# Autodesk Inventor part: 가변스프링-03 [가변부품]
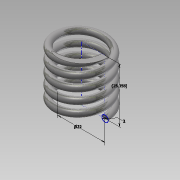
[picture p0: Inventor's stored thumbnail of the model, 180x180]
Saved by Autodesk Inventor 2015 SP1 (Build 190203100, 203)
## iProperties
Created: 2014-12
Part Number: 가변스프링-03 [가변부품]
Material: 강철, 탄소
Document SubType Name: Modeling
Designer: jhkwon
Density: 7.85 g/cm^3
Appearance: 반연마
Mass: 18.6941 g
Surface Area: 32.4032 cm^2
Volume: 2.38141 cm^3
Author: jhkwon
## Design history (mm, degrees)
sketch "스케치1"
  geometry: L1 (0, 0)-(-11, 0); L2 (-11, 0)-(-11, 25.358); L3 (-11, 25.358)-(0, 25.358); L4 (0, 25.358)-(0, 0); C1 r 1.5 at (-11, 0); 1 further point
  constraints: 8 end point, 2 coincident, 2 parallel, 1 centre point, 1 horizontal, 1 perpendicular
  dimensions: "d0" = 3 diameter of C1; "d1" = 22 diameter of L2 L4; "d4" = 25.35829 distance of L1.end L2.end (derived)
feature "코일1" sketch "스케치1" pitch "d5" = 10; turns "d7" = 5; dims "d6" = 25.35829 (= d4), "d8" = 0, angle "d9" = 90 deg, angle "d10" = 90 deg, "d11" = 0, "d12" = 0
sketch "스케치2"
  geometry: L1 (12.5, 0)-(9.5, 0) reference; 1 further point
  constraints: 1 horizontal alignment
extrude "돌출1" cut sketch "스케치2" distance "d13" = 10; taper "d14" = 0 deg
node "작업 평면1"
sketch "스케치3"
  geometry: L1 (0, 0)-(3, 0) reference; 1 further point
  constraints: 1 horizontal alignment
extrude "돌출2" cut sketch "스케치3" distance "d15" = 10; taper "d16" = 0 deg
node "솔리드1"
node "절단 모서리 투영1"
node "절단 모서리 투영2"
